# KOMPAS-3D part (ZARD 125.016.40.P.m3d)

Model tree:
1. Булева операция:1
2. Булева операция:2
3. Булева операция:3
4. Булева операция:4
5. Булева операция:5
6. Булева операция:6
7. Булева операция:7
8. Булева операция:8
9. Булева операция:9
10. Булева операция:10
11. Булева операция:11
12. Булева операция:12
13. Булева операция:13
14. Булева операция:14
15. Булева операция:15
16. Булева операция:16
